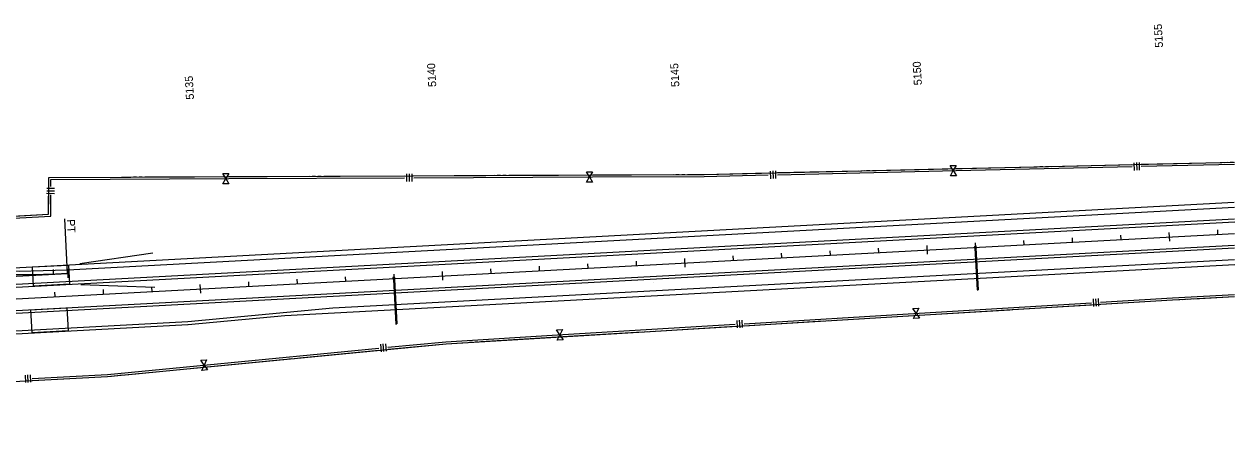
# Model space of a CAD drawing. Extents: x 192699 to 285914, y 194342 to 233219.
# Drawn here: x 259027 to 261522, y 216374 to 217251 of the extents above; entities that cross this region are included whole.
import ezdxf

# ---------------------------------------------------------------- set-up
doc = ezdxf.new("R2010")
doc.units = 0
for name, color, linetype in [('CENT LINE', 7, 'Continuous'), ('CURVE DATA', 7, 'Continuous'), ('CURVE LINE', 7, 'Continuous'), ('Dimentions for MOT', 7, 'Continuous'), ('DRAINAGE', 7, 'Continuous'), ('GUARDRAIL', 7, 'Continuous'), ('R-W - CofA', 7, 'Continuous'), ('ROAD', 7, 'Continuous'), ('SHOULDER', 7, 'Continuous'), ('STATIONING1', 7, 'Continuous'), ('STATIONING2', 7, 'Continuous')]:
    doc.layers.add(name, color=color, linetype=linetype)

msp = doc.modelspace()

# ---------------------------------------------------------------- linework, layer by layer
at = {"layer": 'CENT LINE'}
for p, q in [((255599.6, 216502.3), (261521.8, 216819.6)), ((259116.9, 216737.3), (259116.9, 216737.3))]:
    msp.add_line(p, q, dxfattribs=at)
msp.add_arc((259014.7, 218644.5), 1909.9, 261.0666, 273.0666, dxfattribs=at)
at = {"layer": 'CURVE DATA'}
msp.add_lwpolyline([(259116.9, 216737.3), (259110.9, 216849.6)], dxfattribs=at)
at = {"layer": 'CURVE LINE'}
msp.add_line((258916.4, 216726.6), (259116.9, 216737.3), dxfattribs=at)
at = {"layer": 'Dimentions for MOT'}
msp.add_line((260325, 216717.9), (260325, 216717.9), dxfattribs=at)
at = {"layer": 'DRAINAGE'}
for p, q in [((260986.9, 216788.9), (260991.5, 216703.1)), ((260988.9, 216789.1), (260993.5, 216703.2)), ((259788.6, 216724.7), (259793.5, 216632.9)), ((259790.6, 216724.9), (259795.5, 216633))]:
    msp.add_line(p, q, dxfattribs=at)
for points in [[(260985.9, 216788.9), (260989.9, 216789.1), (260989.6, 216793.1), (260985.7, 216792.9)], [(259787.6, 216724.7), (259791.6, 216724.9), (259791.4, 216728.9), (259787.4, 216728.7)]]:
    msp.add_lwpolyline(points, close=True, dxfattribs=at)
for points in [[(260991.5, 216703.1), (260993.5, 216703.2)], [(259793.5, 216632.9), (259795.5, 216633)]]:
    msp.add_lwpolyline(points, dxfattribs=at)
at = {"layer": 'GUARDRAIL'}
for p, q in [((259142.1, 216757.9), (259292.7, 216779.7)), ((259144.4, 216714.6), (259296.5, 216709))]:
    msp.add_line(p, q, dxfattribs=at)
at = {"layer": 'R-W - CofA'}
for p, q in [((260935.7, 216959.5), (260948.1, 216959.8)), ((260942.1, 216948.9), (260935.7, 216959.5)), ((260948.1, 216959.8), (260942.1, 216948.9)), ((261314.5, 216965.3), (261314.9, 216949.5)), ((261319.8, 216965.5), (261320.1, 216949.6)), ((261325, 216965.6), (261325.4, 216949.8)), ((259442.9, 216932.5), (259436.6, 216943.3)), ((259436.6, 216943.3), (259449.1, 216943.3)), ((259436.7, 216921.7), (259442.9, 216932.5)), ((259449.1, 216943.3), (259442.9, 216932.5)), ((259442.9, 216932.5), (259449.2, 216921.8)), ((259815.5, 216942.2), (259815.6, 216926.3)), ((259820.8, 216942.2), (259820.9, 216926.4)), ((259826.1, 216942.2), (259826.1, 216926.4)), ((260186.3, 216946.7), (260198.7, 216946.8)), ((260192.5, 216936), (260186.3, 216946.7)), ((260186.4, 216925.2), (260192.5, 216936)), ((260198.7, 216946.8), (260192.5, 216936)), ((260192.5, 216936), (260198.8, 216925.3)), ((260565, 216948.1), (260565.4, 216932.3)), ((260570.3, 216948.3), (260570.7, 216932.4)), ((260575.6, 216948.4), (260575.9, 216932.6)), ((260936.1, 216938), (260942.1, 216948.9)), ((260948.6, 216938.3), (260936.1, 216938)), ((260942.1, 216948.9), (260948.6, 216938.3)), ((259073.7, 216902.2), (259089.6, 216902.1)), ((259073.8, 216912.8), (259089.6, 216912.7)), ((259073.8, 216907.5), (259089.6, 216907.4)), ((259449.2, 216921.8), (259436.7, 216921.7)), ((260198.8, 216925.3), (260186.4, 216925.2)), ((261230.4, 216684.6), (261231.4, 216669.1)), ((261235.6, 216685), (261236.5, 216669.4)), ((261240.8, 216685.3), (261241.7, 216669.8)), ((260859.1, 216665.1), (260871.3, 216665.8)), ((260865.8, 216654.9), (260859.1, 216665.1)), ((260860.4, 216644), (260865.8, 216654.9)), ((260871.3, 216665.8), (260865.8, 216654.9)), ((260865.8, 216654.9), (260872.5, 216644.7)), ((260496, 216640.4), (260497, 216624.9)), ((260501.2, 216640.7), (260502.1, 216625.2)), ((260506.4, 216641), (260507.3, 216625.5)), ((260872.5, 216644.7), (260860.4, 216644)), ((260124.7, 216620.8), (260136.9, 216621.5)), ((260131.4, 216610.6), (260124.7, 216620.8)), ((260126, 216599.7), (260131.4, 216610.6)), ((260136.9, 216621.5), (260131.4, 216610.6)), ((260131.4, 216610.6), (260138.1, 216600.5)), ((259761.6, 216591.2), (259763.1, 216575.8)), ((259766.7, 216591.7), (259768.2, 216576.3)), ((259771.9, 216592.2), (259773.4, 216576.8)), ((260138.1, 216600.5), (260126, 216599.7)), ((259391.2, 216558.2), (259403.3, 216559.4)), ((259398.3, 216548.3), (259391.2, 216558.2)), ((259403.3, 216559.4), (259398.3, 216548.3)), ((259029.2, 216527.7), (259030.1, 216512.2)), ((259034.4, 216528), (259035.2, 216512.5)), ((259039.6, 216528.3), (259040.4, 216512.8)), ((259393.2, 216537.2), (259398.3, 216548.3)), ((259405.4, 216538.4), (259393.2, 216537.2)), ((259398.3, 216548.3), (259405.4, 216538.4))]:
    msp.add_line(p, q, dxfattribs=at)
for points in [[(258419.1, 216949.4), (258731.2, 216840.3), (259077.8, 216858.9), (259078.2, 216935), (260428.9, 216941.3), (261521.8, 216966.4)], [(260775.4, 216949.3), (260948.2, 216953.2)], [(260948.2, 216953.2), (261114.8, 216957.1)], [(260948.3, 216949), (261310.5, 216957.3)], [(261120.2, 216957.2), (261126.6, 216957.3)], [(261132, 216957.5), (261138.4, 216957.6)], [(261143.8, 216957.7), (261310.4, 216961.6)], [(261329.3, 216962), (261495.9, 216965.8)], [(261329.4, 216957.8), (261521.8, 216962.2)], [(261501.3, 216965.9), (261507.7, 216966.1)], [(261513.1, 216966.2), (261519.5, 216966.4)], [(259078.1, 216916), (259078.2, 216935)], [(259078.2, 216935), (259247.3, 216935.8)], [(259082.3, 216916), (259082.4, 216930.8)], [(259082.4, 216930.8), (259449.1, 216932.5)], [(259252.6, 216935.9), (259259.1, 216935.9)], [(259264.4, 216935.9), (259270.9, 216935.9)], [(259276.2, 216936), (259449.1, 216936.8)], [(259449.1, 216936.8), (259615.7, 216937.5)], [(259449.1, 216932.5), (259811.3, 216934.2)], [(259621.1, 216937.6), (259627.5, 216937.6)], [(259632.9, 216937.6), (259639.3, 216937.6)], [(259644.7, 216937.7), (259811.3, 216938.4)], [(259830.3, 216938.5), (259996.9, 216939.3)], [(259830.3, 216934.3), (260198.7, 216936)], [(260002.3, 216939.3), (260008.7, 216939.4)], [(260014.1, 216939.4), (260020.5, 216939.4)], [(260025.9, 216939.4), (260198.7, 216940.2)], [(260198.7, 216940.2), (260365.4, 216941)], [(260198.7, 216936), (260429, 216937.1), (260561, 216940.1)], [(260370.7, 216941), (260377.2, 216941.1)], [(260382.5, 216941.1), (260388.9, 216941.1)], [(260394.3, 216941.2), (260428.9, 216941.3), (260560.9, 216944.3)], [(260579.9, 216944.8), (260746.5, 216948.6)], [(260580, 216940.6), (260948.3, 216949)], [(260751.8, 216948.7), (260758.3, 216948.9)], [(260763.6, 216949), (260770.1, 216949.1)], [(258775.8, 216838.5), (259082, 216854.9), (259082.2, 216898.8)], [(258970.9, 216853.2), (259077.8, 216858.9), (259078, 216899)], [(258299, 216373.7), (258500.4, 216487.5), (259199.4, 216524.9), (259896.8, 216592.3), (261394.1, 216682.6), (261521.8, 216689.4)], [(261245.4, 216677.8), (261393.9, 216686.7), (261521.8, 216693.6)], [(261245.6, 216673.6), (261394.1, 216682.6), (261408.9, 216683.4)], [(261414.1, 216683.7), (261420.4, 216684)], [(261425.7, 216684.3), (261432, 216684.6)], [(261437.2, 216684.9), (261521.8, 216689.4)], [(260511, 216633.5), (260871.9, 216655.3)], [(260871.9, 216655.3), (261226.8, 216676.6)], [(260872.2, 216651.1), (261035.4, 216661)], [(261040.7, 216661.3), (261047, 216661.7)], [(261052.2, 216662), (261058.5, 216662.4)], [(261063.8, 216662.7), (261227, 216672.5)], [(260137.5, 216611), (260492.4, 216632.4)], [(260329.4, 216618.4), (260492.6, 216628.3)], [(260511.2, 216629.4), (260674.5, 216639.2)], [(260679.7, 216639.5), (260686, 216639.9)], [(260691.3, 216640.2), (260697.6, 216640.6)], [(260702.8, 216640.9), (260872.2, 216651.1)], [(259776.8, 216584.9), (259896.5, 216596.5), (260137.5, 216611)], [(259968.4, 216596.7), (260137.8, 216606.9)], [(260137.8, 216606.9), (260301, 216616.7)], [(260306.3, 216617), (260312.6, 216617.4)], [(260317.8, 216617.7), (260324.1, 216618.1)], [(259404.4, 216548.9), (259758.2, 216583.1)], [(259595.8, 216563.3), (259758.6, 216579)], [(259777.2, 216580.8), (259896.8, 216592.3), (259940.1, 216595)], [(259945.3, 216595.3), (259951.6, 216595.6)], [(259956.9, 216596), (259963.2, 216596.3)], [(259404.8, 216544.8), (259567.5, 216560.5)], [(259572.8, 216561), (259579.1, 216561.6)], [(259584.3, 216562.1), (259590.6, 216562.7)], [(259044.1, 216520.8), (259199.1, 216529.1), (259404.4, 216548.9)], [(259224.4, 216527.4), (259230.7, 216528)], [(259235.9, 216528.5), (259404.8, 216544.8)], [(259044.3, 216516.6), (259199.4, 216524.9), (259207.6, 216525.7)], [(259212.9, 216526.2), (259219.1, 216526.8)]]:
    msp.add_lwpolyline(points, dxfattribs=at)
at = {"layer": 'ROAD'}
for p, q in [((259116.5, 216744.8), (261521.8, 216873.7)), ((255599.6, 216532.4), (261521.8, 216849.6)), ((255599.6, 216472.3), (261521.8, 216789.6)), ((259043.6, 216750.4), (259118.5, 216754.4)), ((259663.5, 216666), (261521.8, 216765.5)), ((259045.7, 216711.5), (259120.6, 216715.5)), ((259040.4, 216662.1), (259115.3, 216666.1)), ((258735.5, 216604.2), (259364.6, 216637.9)), ((259042.9, 216615.2), (259117.8, 216619.2))]:
    msp.add_line(p, q, dxfattribs=at)
for points in [[(259118.5, 216754.4), (259120.6, 216715.5)], [(259043.6, 216750.4), (259045.7, 216711.5)], [(259040.4, 216662.1), (259042.9, 216615.2)], [(259115.3, 216666.1), (259117.8, 216619.2)], [(259364.6, 216637.9), (259663.5, 216666)]]:
    msp.add_lwpolyline(points, dxfattribs=at)
msp.add_arc((259014.7, 218644.5), 1902.4, 261.0666, 273.0666, dxfattribs=at)
at = {"layer": 'SHOULDER'}
for p, q in [((258993, 216748.2), (261521.2, 216883.7)), ((255599.9, 216526.4), (261522.1, 216843.7)), ((255599.3, 216478.3), (261521.5, 216795.6)), ((259564.3, 216650.6), (261522.3, 216755.5)), ((258735.8, 216598.2), (259364.9, 216631.9)), ((259365.1, 216632), (259564.3, 216650.6))]:
    msp.add_line(p, q, dxfattribs=at)
at = {"layer": 'STATIONING1'}
for points in [[(261486.6, 216826.7), (261487, 216817.7)], [(261087.1, 216805.3), (261087.6, 216796.3)], [(261187, 216810.7), (261187.5, 216801.7)], [(261286.8, 216816), (261287.3, 216807)], [(261386.7, 216821.4), (261387.7, 216803.4)], [(260587.8, 216778.6), (260588.3, 216769.6)], [(260687.7, 216783.9), (260688.2, 216774.9)], [(260787.6, 216789.3), (260788, 216780.3)], [(260887.4, 216794.6), (260888.4, 216776.7)], [(260987.3, 216800), (260987.8, 216791)], [(260088.6, 216751.8), (260089, 216742.8)], [(260188.4, 216757.2), (260188.9, 216748.2)], [(260288.3, 216762.5), (260288.8, 216753.5)], [(260388.1, 216767.9), (260389.1, 216749.9)], [(260488, 216773.2), (260488.5, 216764.2)], [(259689.1, 216730.4), (259689.6, 216721.4)], [(259789, 216735.8), (259789.5, 216726.8)], [(259888.9, 216741.1), (259889.8, 216723.2)], [(259988.7, 216746.5), (259989.2, 216737.5)], [(259189.9, 216703.7), (259190.3, 216694.7)], [(259289.7, 216709), (259290.2, 216700)], [(259389.6, 216714.4), (259390.5, 216696.4)], [(259489.4, 216719.7), (259489.9, 216710.7)], [(259589.3, 216725.1), (259589.8, 216716.1)], [(259090, 216698.3), (259090.5, 216689.3)]]:
    msp.add_lwpolyline(points, dxfattribs=at)
at = {"layer": 'STATIONING2'}
for points in [[(259087.1, 216745), (259087.4, 216736)], [(259116.4, 216746.3), (259116.9, 216737.3)], [(259116.4, 216746.3), (259117.4, 216728.3)]]:
    msp.add_lwpolyline(points, dxfattribs=at)

# ---------------------------------------------------------------- texts
at = {"layer": 'CURVE DATA'}
msp.add_text('PT', height=16.5, rotation=273.0666, dxfattribs=at).set_placement((259115.2, 216848.3))
at = {"layer": 'STATIONING1'}
for s, p in [('5155', (261374.5, 217202.7)), ('5140', (259876.7, 217121.8)), ('5145', (260377.7, 217121.8)), ('5150', (260877.5, 217125.4)), ('5135', (259377.4, 217095.7))]:
    msp.add_text(s, height=16.5, rotation=93.0667, dxfattribs=at).set_placement(p)

doc.saveas('drawing.dxf')
